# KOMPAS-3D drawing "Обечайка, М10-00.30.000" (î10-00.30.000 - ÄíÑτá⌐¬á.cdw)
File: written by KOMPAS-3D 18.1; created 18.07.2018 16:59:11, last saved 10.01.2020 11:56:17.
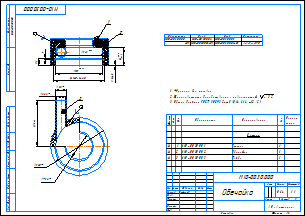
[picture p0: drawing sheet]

Sheet 1: A3, landscape

Document properties: Автор: Милов; Полное имя файла: D:\Magna\Магна Ins\Магна ins 10\М10-00.00.000\3Д\М10-00.30.000 - Обечайка.cdw; Масса: 0.639069

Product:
- Part/product: Обечайка  | designation М10-00.30.000
    Масса: 0.639069
  - Component [detail]: Труба  | designation М10-00.30.003  | pos. 3  | Масса: 0.0208235; Раздел спецификации: Детали; Форматы листов документа: A4; source file: М10-00.30.003 - Труба.cdw, М10-00.30.003 - Труба.m3d
  - Component [detail]: Стенка  | designation М10-00.30.001  | pos. 1  | Материал: Полипропилен  ГОСТ 26996-86 (density 900 kg/m3); Масса: 0.209599; Раздел спецификации: Детали; Форматы листов документа: A4; source file: М10-00.30.001 - Стенка.cdw, М10-00.30.001 - Стенка.m3d
  - Component [detail]: Обечайка  | designation М10-00.30.002  | pos. 2  | Масса: 0.408646; Раздел спецификации: Детали; Форматы листов документа: A4; source file: М10-00.30.002 - Обечайка.m3d
- Part/product: Обечайка  | designation М10-00.30.000  | pos. 0
    Масса: 0.778327
    Раздел спецификации: Сборочные единицы
    Форматы листов документа: A3
    source file: \\192.168.87.28\Konstructor_doc\Магна\Магна Ins\Магна ins 10\М10-00.00.000\3Д\М10-00.30.000 - Обечайка.cdw
  - Component [detail]: Труба ПВХ  | designation М13-01.30.003  | pos. 3  | Масса: 0.0162255; Раздел спецификации: Детали; Форматы листов документа: A4; Примечание: См. табл.; source file: ..\..\..\Магна ins 13\М13-01.00.000 ПВХ\Чертежи Компас\М13-01.30.003 - Труба.cdw, М10-00.30.003 - Труба.m3d
  - Component [detail]: Стенка ПВХ  | designation М10-10.30.001  | pos. 1  | Материал: Полипропилен  ГОСТ 26996-86 (density 0 kg/m3); Раздел спецификации: Детали; Форматы листов документа: A4; source file: М10-00.30.001 - Стенка.m3d
  - Component [detail]: Обечайка ПВХ  | designation М13-01.30.002  | pos. 2  | Масса: 0.759467; Раздел спецификации: Детали; Форматы листов документа: A4; Примечание: См. табл.; source file: ..\..\..\Магна ins 13\М13-01.00.000 ПВХ\Чертежи Компас\М13-01.30.002 - Обечайка.cdw, М10-00.30.002 - Обечайка.cdw, М10-00.30.002 - Обечайка.m3d
  - Body: Тело 7
      Материал: Полипропилен  ГОСТ 26996-86 (density 900 kg/m3)

Title block, sheet 1: Наименование: Обечайка; designation: М10-00.30.000; Масса: 0,64; scale: 1:1; Количество листов документа: 1; organisation: АО «Астерион»; Форматы листов документа: A3; stored path: Z:\Магна\Магна Ins\Магна ins 10\М10-00.00.000\3Д\М10-00.30.000 - Обечайка.cdw; Разработал: Лифлянд

Views: Вид 1, Местный разрез 1, Спереди, Проекционный вид 2, Вид:1
Referenced files in D:\Magna\Магна Ins\Магна ins 10\М10-00.00.000\3Д\: Труба 160 S=14,6 FV PPR ф. FV PLAST.m3d, Труба 32 PN10 S=2,9 FV PPR ф. FV PLAST.m3d, М10-00.30.001 - Стенка.m3d, М10-00.30.002 - Обечайка.m3d, М10-00.30.001 - Стенка.cdw, М10-00.30.003 - Труба.m3d, М10-00.30.003 - Труба.cdw, М10-00.30.000 - Обечайка.a3d
Referenced files in Z:\Магна\Магна Ins\Магна ins 10\М10-00.00.000\3Д\: М10-00.30.000 - Обечайка.a3d, М10-00.30.001 - Стенка.m3d, Труба 160 S=14,6 FV PPR ф. FV PLAST.m3d, Труба 32 PN10 S=2,9 FV PPR ф. FV PLAST.m3d
Referenced files in Z:\1 ПКИ 3D\Полипропиленовые фитинги, трубы\Трубы\: Труба 160 S=14,6 FV PPR ф. FV PLAST.m3d, Труба 32 PN10 S=2,9 FV PPR ф. FV PLAST.m3d
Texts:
  Поз.2
  Поз.3
  АкваProf190
  Стенка
  Труба
  Труба 160 S=14,6 / FV PPR ф. "FV PLAST"
  Труба 32 PN10 S=2,9 FV PPR ф. "FV PLAST"
Dimensions and other numbers on the sheet: 32; 126; 3; 160; 73,2; 26,2; 1; 131; 21; 4; 140; 51; 2,5; 2; -01; 141; 1:1; 0,64

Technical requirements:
  *Размеры для справок.
  Шероховатость дорабатываемых поверхностей  Ra 3,2 .
  Общие допуски ГОСТ 30893.2-mK (H14, h14,  t2/2).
